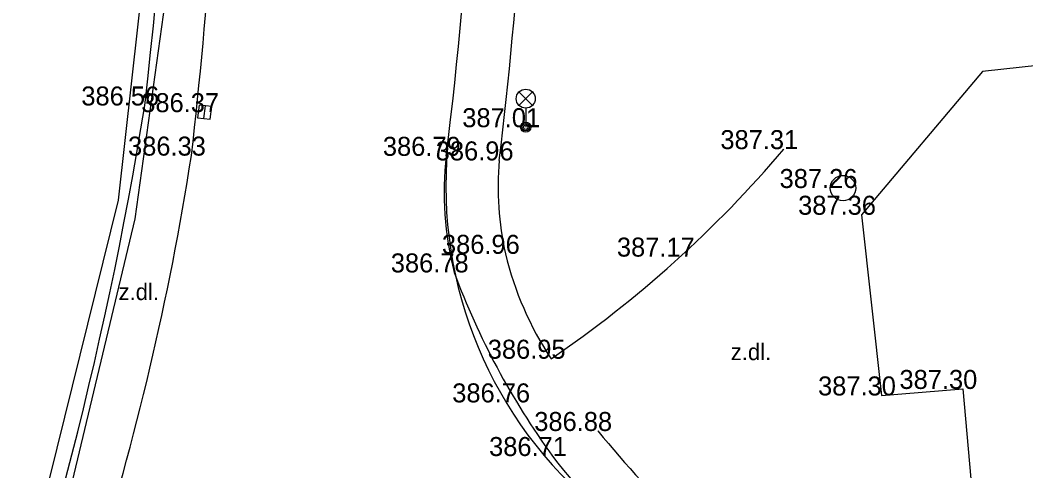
# Model space of a CAD drawing. Extents: x -438233 to -437334, y -1133133 to -1132623.
# Drawn here: x -438163.87 to -438124.22, y -1132932.56 to -1132914.78 of the extents above; entities that cross this region are included whole.
import ezdxf

# ---------------------------------------------------------------- set-up
doc = ezdxf.new("R2010")
doc.units = 0
for name, color, linetype in [('Vrstva 1', 7, 'Continuous'), ('Vrstva 10', 7, 'Continuous'), ('Vrstva 11', 7, 'Continuous'), ('Vrstva 27', 7, 'Continuous'), ('Vrstva 3', 7, 'Continuous'), ('Vrstva 33', 7, 'Continuous'), ('Vrstva 40', 7, 'Continuous'), ('Vrstva 5', 7, 'Continuous'), ('Vrstva 53', 7, 'Continuous')]:
    doc.layers.add(name, color=color, linetype=linetype)

msp = doc.modelspace()

# ---------------------------------------------------------------- linework, layer by layer
at = {"layer": 'Vrstva 1'}
for p, q in [((-438158.957, -1132918.149), (-438158.957, -1132918.149)), ((-438156.595, -1132918.413), (-438156.595, -1132918.413)), ((-438143.939, -1132919.006), (-438143.939, -1132919.006)), ((-438133.765, -1132919.871), (-438133.765, -1132919.871)), ((-438157.116, -1132920.127), (-438157.116, -1132920.127)), ((-438147.07, -1132920.136), (-438147.07, -1132920.136)), ((-438144.985, -1132920.316), (-438144.985, -1132920.316)), ((-438131.431, -1132921.405), (-438131.431, -1132921.405)), ((-438130.7, -1132922.46), (-438130.7, -1132922.46)), ((-438144.742, -1132924.002), (-438144.742, -1132924.002)), ((-438137.844, -1132924.111), (-438137.844, -1132924.111)), ((-438146.757, -1132924.735), (-438146.757, -1132924.735)), ((-438142.935, -1132928.139), (-438142.935, -1132928.139)), ((-438126.705, -1132929.331), (-438126.705, -1132929.331)), ((-438144.335, -1132929.862), (-438144.335, -1132929.862)), ((-438129.914, -1132929.587), (-438129.914, -1132929.587)), ((-438141.101, -1132930.989), (-438141.101, -1132930.989)), ((-438142.882, -1132931.977), (-438142.882, -1132931.977))]:
    msp.add_line(p, q, dxfattribs=at)
msp.add_arc((-438130.547, -1132921.319), 16.541, 174.8014, 230.4908, dxfattribs=at)
at = {"layer": 'Vrstva 10'}
for centre, radius, start, end in [((-438384.633, -1132894.507), 228.955, 353.57529, 2.49989), ((-438319.386, -1132898.79), 173.633, 352.93848, 0.58519), ((-438267.774, -1132902.859), 111.997, 342.38526, 351.13063), ((-438134.402, -1132921.584), 12.75, 173.4789, 194.308), ((-438118.671, -1132914.365), 29.94, 200.266, 216.0341), ((-438106.646, -1132904.004), 45.777, 217.6664, 231.6958)]:
    msp.add_arc(centre, radius, start, end, dxfattribs=at)
at = {"layer": 'Vrstva 11'}
for centre, radius, start, end in [((-438353.312, -1132895.52), 195.668, 353.35896, 3.21989), ((-438315.621, -1132899.594), 171.89, 353.07606, 359.53813), ((-438312.067, -1132893.395), 155.099, 339.71616, 350.81615), ((-438168.696, -1132890.349), 45.735, 304.2813, 319.7966), ((-438132.457, -1132921.341), 12.57, 175.3221, 192.2215), ((-438132.131, -1132920.957), 12.973, 193.5754, 213.6151), ((-438092.402, -1132890.449), 63.365, 219.77595, 229.22236)]:
    msp.add_arc(centre, radius, start, end, dxfattribs=at)
at = {"layer": 'Vrstva 27'}
msp.add_line((-438156.625, -1132918.661), (-438156.565, -1132918.165), dxfattribs=at)
msp.add_lwpolyline([(-438156.376, -1132918.691), (-438156.317, -1132918.194), (-438156.814, -1132918.135), (-438156.873, -1132918.632)], close=True, dxfattribs=at)
msp.add_circle((-438131.431, -1132921.405), 0.5, dxfattribs=at)
at = {"layer": 'Vrstva 33'}
for p, q in [((-438144.204, -1132918.146), (-438143.674, -1132917.616)), ((-438144.204, -1132917.616), (-438143.674, -1132918.146)), ((-438143.939, -1132918.256), (-438143.939, -1132919.006))]:
    msp.add_line(p, q, dxfattribs=at)
for centre, radius in [((-438143.939, -1132917.881), 0.375), ((-438143.939, -1132919.006), 0.2), ((-438143.939, -1132919.006), 0.145), ((-438143.939, -1132919.006), 0.0876)]:
    msp.add_circle(centre, radius, dxfattribs=at)
at = {"layer": 'Vrstva 5'}
for p, q in [((-438130.7, -1132922.46), (-438129.914, -1132929.587)), ((-438129.914, -1132929.587), (-438126.705, -1132929.331)), ((-438126.705, -1132929.331), (-438125.927, -1132938.095))]:
    msp.add_line(p, q, dxfattribs=at)
msp.add_lwpolyline([(-438111.968, -1132915.287), (-438125.93, -1132916.81), (-438130.7, -1132922.46)], dxfattribs=at)
at = {"layer": 'Vrstva 53'}
for points in [[(-438164.46, -1132942.23), (-438162.24, -1132934.78), (-438159.33, -1132922.62), (-438158.02, -1132913.14), (-438157.41, -1132899.84), (-438158.29, -1132898.64), (-438160.31, -1132897.85), (-438163, -1132896.01), (-438164.044, -1132894.731)], [(-438171.57, -1132956.51), (-438167.71, -1132946.4), (-438163.02, -1132934.11), (-438159.99, -1132921.89), (-438158.96, -1132912.58)]]:
    msp.add_lwpolyline(points, dxfattribs=at)

# ---------------------------------------------------------------- texts
at = {"layer": 'Vrstva 3'}
for s, p in [('386.56 ', (-438161.457, -1132918.149)), ('386.37 ', (-438159.095, -1132918.413)), ('387.01 ', (-438146.439, -1132919.006)), ('387.31 ', (-438136.265, -1132919.871)), ('386.33 ', (-438159.616, -1132920.127)), ('386.79 ', (-438149.57, -1132920.136)), ('386.96 ', (-438147.485, -1132920.316)), ('387.26 ', (-438133.931, -1132921.405)), ('387.36 ', (-438133.2, -1132922.46)), ('386.96 ', (-438147.242, -1132924.002)), ('387.17 ', (-438140.344, -1132924.111)), ('386.78 ', (-438149.257, -1132924.735)), ('386.95 ', (-438145.435, -1132928.139)), ('387.30 ', (-438129.205, -1132929.331)), ('386.76 ', (-438146.835, -1132929.862)), ('387.30 ', (-438132.414, -1132929.587)), ('386.88 ', (-438143.601, -1132930.989)), ('386.71 ', (-438145.382, -1132931.977))]:
    msp.add_text(s, height=0.75, dxfattribs=at).set_placement(p)
at = {"layer": 'Vrstva 40'}
for p in [(-438159.99, -1132925.825), (-438135.855, -1132928.195)]:
    msp.add_text('z.dl.', height=0.65, dxfattribs=at).set_placement(p)

doc.saveas('drawing.dxf')
